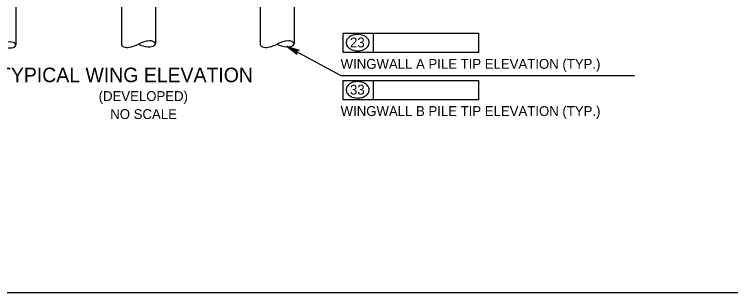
# Model space of a CAD drawing. Extents: x 635440 to 640306, y 296653 to 298484.
# Drawn here: x 638838.2 to 639056.4, y 297856.5 to 297941.3 of the extents above; entities that cross this region are included whole.
import ezdxf

# ---------------------------------------------------------------- set-up
doc = ezdxf.new("R2010")
doc.units = 0
for name, color, linetype in [('2', 7, 'Continuous'), ('4', 7, 'Continuous'), ('5', 7, 'Continuous')]:
    doc.layers.add(name, color=color, linetype=linetype)

msp = doc.modelspace()

# ---------------------------------------------------------------- linework, layer by layer
at = {"layer": '2'}
msp.add_line((639261.46, 297856.46), (638475.46, 297856.46), dxfattribs=at)
at = {"layer": '4'}
for p, q in [((638923.43, 298004.99), (638923.43, 297932.35)), ((638913.09, 298001.54), (638913.09, 297932.07)), ((638881.17, 297991.28), (638881.17, 297932.35)), ((638870.83, 297986.54), (638870.83, 297932.07)), ((638838.64, 297978), (638838.64, 297931.96))]:
    msp.add_line(p, q, dxfattribs=at)
for centre, major_axis, start_param, end_param in [((638836.81, 297931.96), (1.83, 0), 4.455588, 8.110783), ((638872.66, 297932.12), (-1.83, -0.05), 0, 1.827597), ((638870.76, 297934.66), (-7.31, -0.2), 1.89032, 2.356194), ((638881.24, 297929.77), (7.31, 0.2), 1.89032, 2.356194), ((638881.1, 297934.94), (7.31, 0.2), 3.926991, 4.392865), ((638879.34, 297932.3), (1.83, 0.05), 4.455588, 8.110783), ((638914.92, 297932.12), (-1.83, -0.05), 0, 1.827597), ((638913.02, 297934.66), (-7.31, -0.2), 1.89032, 2.356194), ((638923.5, 297929.77), (7.31, 0.2), 1.89032, 2.356194), ((638923.36, 297934.94), (7.31, 0.2), 3.926991, 4.392865), ((638921.6, 297932.3), (1.83, 0.05), 4.455588, 8.110783)]:
    msp.add_ellipse(centre, major_axis=major_axis, ratio=0.5, start_param=start_param, end_param=end_param, dxfattribs=at)
at = {"layer": '5'}
for p, q in [((638938.41, 297935.52), (638979.62, 297935.52)), ((638938.41, 297929.62), (638938.41, 297935.52)), ((638947.58, 297929.62), (638947.58, 297935.52)), ((638979.62, 297935.52), (638979.62, 297929.62)), ((638921.3, 297931.48), (638937.68, 297922.68)), ((638979.62, 297929.62), (638938.41, 297929.62)), ((638937.68, 297922.68), (639027.1, 297922.68)), ((638938.41, 297921.14), (638979.62, 297921.14)), ((638938.41, 297915.24), (638938.41, 297921.14)), ((638947.58, 297915.24), (638947.58, 297921.14)), ((638979.62, 297921.14), (638979.62, 297915.24)), ((638979.62, 297915.24), (638938.41, 297915.24))]:
    msp.add_line(p, q, dxfattribs=at)
msp.add_lwpolyline([(638921.3, 297931.48), (638924.92, 297930.33), (638924.57, 297930.29), (638924.32, 297930.14), (638924.17, 297929.94), (638924.09, 297929.7), (638924.1, 297929.41), (638924.26, 297929.1), (638921.3, 297931.48), (638924.1, 297929.41), (638924.09, 297929.7), (638921.3, 297931.48), (638924.17, 297929.94), (638924.32, 297930.14), (638921.3, 297931.48), (638924.57, 297930.29)], dxfattribs=at)
for centre, radius, start, end in [((638941.92, 297932.21), 2.76, 125.6316, 149.9767), ((638942.45, 297931.48), 3.66, 106.5358, 125.6316), ((638942.79, 297930.32), 4.87, 90, 106.5358), ((638942.79, 297930.32), 4.87, 73.4642, 90), ((638943.14, 297931.48), 3.66, 54.3684, 73.4642), ((638943.66, 297932.21), 2.76, 30.0233, 54.3684), ((638941.11, 297932.68), 1.83, 149.9767, 180), ((638941.11, 297932.68), 1.83, 180, 210.0233), ((638944.47, 297932.68), 1.83, 0, 30.0233), ((638944.47, 297932.68), 1.83, 329.9767, 0), ((638941.92, 297933.14), 2.76, 210.0233, 234.3684), ((638942.45, 297933.88), 3.66, 234.3684, 253.4642), ((638942.79, 297935.04), 4.87, 253.4642, 270), ((638942.79, 297935.04), 4.87, 270, 286.5358), ((638943.14, 297933.88), 3.66, 286.5358, 305.6316), ((638943.66, 297933.14), 2.76, 305.6316, 329.9767), ((638941.11, 297918.3), 1.83, 149.9767, 180), ((638941.92, 297917.83), 2.76, 125.6316, 149.9767), ((638942.45, 297917.1), 3.66, 106.5358, 125.6316), ((638942.79, 297915.94), 4.87, 90, 106.5358), ((638942.79, 297915.94), 4.87, 73.4642, 90), ((638943.14, 297917.1), 3.66, 54.3684, 73.4642), ((638943.66, 297917.83), 2.76, 30.0233, 54.3684), ((638944.47, 297918.3), 1.83, 0, 30.0233), ((638941.11, 297918.3), 1.83, 180, 210.0233), ((638941.92, 297918.76), 2.76, 210.0233, 234.3684), ((638943.66, 297918.76), 2.76, 305.6316, 329.9767), ((638944.47, 297918.3), 1.83, 329.9767, 0), ((638942.45, 297919.5), 3.66, 234.3684, 253.4642), ((638942.79, 297920.66), 4.87, 253.4642, 270), ((638942.79, 297920.66), 4.87, 270, 286.5358), ((638943.14, 297919.5), 3.66, 286.5358, 305.6316)]:
    msp.add_arc(centre, radius, start, end, dxfattribs=at)

# ---------------------------------------------------------------- texts
for s, height, p in [('23', 3, (638940.46, 297931.22)), ('WINGWALL A PILE TIP ELEVATION (TYP.)', 3.0001, (638937.6, 297924.7)), ('TYPICAL WING ELEVATION', 4.4294, (638833.54, 297920.62)), ('33', 3, (638940.46, 297916.84)), ('(DEVELOPED)', 3.0001, (638863.89, 297914.89)), ('NO SCALE', 3, (638867.43, 297909.39)), ('WINGWALL B PILE TIP ELEVATION (TYP.)', 3.0001, (638937.6, 297910.32))]:
    msp.add_text(s, height=height, dxfattribs=at).set_placement(p)

doc.saveas('drawing.dxf')
